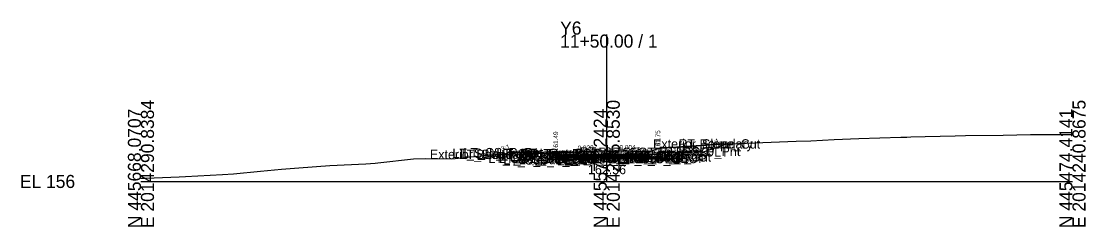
# Model space of a CAD drawing. Extents: x -26 to 203, y -10 to 4529.
# Drawn here: x -25.7 to 202.8, y 2990.3 to 3034.3 of the extents above; entities that cross this region are included whole.
import ezdxf

# ---------------------------------------------------------------- set-up
doc = ezdxf.new("R2010")
doc.units = 0
for name, color, linetype in [('Default', 7, 'Continuous'), ('Exist Cross Section Cell', 7, 'Continuous'), ('Exist XS Center Line Elevation Label', 7, 'Continuous'), ('Exist XS Ground Line', 7, 'Continuous'), ('Prop CMT Conc Surface', 7, 'Continuous'), ('Prop CMT Concrete Structures', 7, 'Continuous'), ('Prop CMT Pvmt Course 1', 7, 'Continuous'), ('Prop CMT Pvmt Course 1 CG', 7, 'Continuous'), ('Prop CMT Pvmt Course 2', 7, 'Continuous'), ('Prop CMT Pvmt Course 3', 7, 'Continuous'), ('Prop CMT Pvmt Surface', 7, 'Continuous'), ('Prop CMT Slope Grass', 7, 'Continuous'), ('Prop CMT Subgrade Earthwork', 7, 'Continuous'), ('Prop XS Earthwork Shape', 7, 'Continuous'), ('Prop XS Hydro Elevations', 7, 'Continuous'), ('Prop XS SE Text', 7, 'Continuous'), ('Prop XS Side Slope Text', 7, 'Continuous'), ('Scratch_Level_0', 7, 'Continuous')]:
    doc.layers.add(name, color=color, linetype=linetype)

msp = doc.modelspace()

# ---------------------------------------------------------------- linework, layer by layer
at = {"layer": 'Exist Cross Section Cell'}
for p, q in [((100, 3000), (100, 3031.48)), ((0, 3000), (100, 3000)), ((100, 3000), (200, 3000))]:
    msp.add_line(p, q, dxfattribs=at)
at = {"layer": 'Exist XS Ground Line'}
msp.add_lwpolyline([(0, 3000.72), (1.06, 3000.72), (8.22, 3001.02), (9.54, 3001.08), (17.48, 3001.5), (19.87, 3001.64), (25.69, 3002.24), (30.2, 3002.63), (33.9, 3002.94), (40.53, 3003.4), (48.25, 3003.8), (50.32, 3003.92), (50.86, 3003.96), (58.53, 3004.82), (61.19, 3004.92), (66.74, 3004.86), (71.52, 3005.33), (74.95, 3005.69), (85.22, 3006.07), (90.92, 3006.21), (96, 3006.42), (100.15, 3006.56), (105.56, 3006.5), (109.28, 3006.38), (110.84, 3007), (111.74, 3007.17), (120.27, 3007.73), (124.22, 3007.99), (128.31, 3008.14), (133.49, 3008.37), (140.64, 3008.62), (143.82, 3008.71), (148.85, 3008.97), (154.15, 3009.24), (163.13, 3009.46), (164.47, 3009.51), (165.27, 3009.53), (168.34, 3009.61), (174.8, 3009.78), (177.05, 3009.84), (185.13, 3009.92), (190.97, 3010.03), (196.73, 3010.09), (200, 3010.05)], dxfattribs=at)
at = {"layer": 'Prop CMT Conc Surface'}
for points in [[(89.06, 3005.49), (89.06, 3005.99), (88.56, 3005.99)], [(91.06, 3005.61), (89.06, 3005.49)], [(109, 3005.82), (111, 3005.75)], [(111, 3005.75), (111, 3006.25), (111.5, 3006.25)]]:
    msp.add_lwpolyline(points, dxfattribs=at)
at = {"layer": 'Prop CMT Concrete Structures'}
for points in [[(91.06, 3005.61), (89.06, 3005.49), (89.06, 3005.99), (88.56, 3005.99)], [(88.56, 3005.99), (88.56, 3004.98), (91.06, 3005.03)], [(91.06, 3005.03), (91.06, 3005.61)], [(109, 3005.82), (111, 3005.75), (111, 3006.25), (111.5, 3006.25)], [(111.5, 3006.25), (111.5, 3005.25), (109, 3005.24)], [(109, 3005.24), (109, 3005.82)]]:
    msp.add_lwpolyline(points, dxfattribs=at)
at = {"layer": 'Prop CMT Pvmt Course 1'}
for points in [[(100, 3005.79), (91.06, 3005.61)], [(91.06, 3005.61), (91.06, 3005.36)], [(91.06, 3005.36), (100, 3005.54)], [(100, 3005.79), (109, 3005.82)], [(100, 3005.54), (100, 3005.79)], [(100, 3005.54), (100, 3005.79)], [(109, 3005.57), (100, 3005.54)], [(109, 3005.82), (109, 3005.57)]]:
    msp.add_lwpolyline(points, dxfattribs=at)
msp.add_lwpolyline([(100, 3005.54), (100, 3005.67), (100, 3005.67), (100, 3005.54)], close=True, dxfattribs=at)
msp.add_lwpolyline([(100, 3005.54), (100, 3005.67), (100, 3005.67), (100, 3005.54)], close=True, dxfattribs=at)
at = {"layer": 'Prop CMT Pvmt Course 1 CG'}
for points in [[(109, 3005.24), (112, 3005.25), (112.33, 3004.92)], [(109, 3004.91), (109, 3005.24)], [(91.06, 3005.03), (88.06, 3004.97), (87.72, 3004.63)], [(87.72, 3004.63), (91.06, 3004.7)], [(91.06, 3004.7), (91.06, 3005.03)], [(112.33, 3004.92), (109, 3004.91)]]:
    msp.add_lwpolyline(points, dxfattribs=at)
at = {"layer": 'Prop CMT Pvmt Course 2'}
for points in [[(100, 3005.54), (91.06, 3005.36)], [(91.06, 3005.36), (91.06, 3005.03)], [(91.06, 3005.03), (100, 3005.21)], [(100, 3005.54), (109, 3005.57)], [(100, 3005.21), (100, 3005.54)], [(100, 3005.21), (100, 3005.54)], [(109, 3005.24), (100, 3005.21)], [(109, 3005.57), (109, 3005.24)]]:
    msp.add_lwpolyline(points, dxfattribs=at)
at = {"layer": 'Prop CMT Pvmt Course 3'}
for points in [[(100, 3005.21), (91.06, 3005.03)], [(100, 3005.21), (109, 3005.24)], [(100, 3004.88), (100, 3005.21)], [(100, 3004.88), (100, 3005.21)], [(109, 3005.24), (109, 3004.91)], [(91.06, 3005.03), (91.06, 3004.7)], [(91.06, 3004.7), (100, 3004.88)], [(109, 3004.91), (100, 3004.88)]]:
    msp.add_lwpolyline(points, dxfattribs=at)
at = {"layer": 'Prop CMT Pvmt Surface'}
for points in [[(100, 3005.79), (91.06, 3005.61)], [(100, 3005.79), (109, 3005.82)]]:
    msp.add_lwpolyline(points, dxfattribs=at)
at = {"layer": 'Prop CMT Slope Grass'}
for points in [[(111.5, 3006.25), (121, 3006.44), (125.82, 3008.05)], [(88.56, 3005.99), (79.06, 3006.18), (77.91, 3005.8)]]:
    msp.add_lwpolyline(points, dxfattribs=at)
at = {"layer": 'Prop CMT Subgrade Earthwork'}
for points in [[(91.06, 3004.7), (87.72, 3004.63), (86.31, 3006.04)], [(109, 3004.91), (112.33, 3004.92), (113.71, 3006.3)], [(100, 3004.88), (91.06, 3004.7)], [(100, 3004.88), (109, 3004.91)]]:
    msp.add_lwpolyline(points, dxfattribs=at)
at = {"layer": 'Prop XS Earthwork Shape'}
for points in [[(121, 3006.44), (125.82, 3008.05), (124.22, 3007.99), (120.27, 3007.73), (111.74, 3007.17), (110.84, 3007), (109.28, 3006.38), (105.56, 3006.5), (100.15, 3006.56), (96, 3006.42), (90.92, 3006.21), (85.22, 3006.07), (85.13, 3006.06), (86.31, 3006.04), (88.56, 3005.99), (89.06, 3005.99), (89.06, 3005.49), (91.06, 3005.61), (100, 3005.79), (109, 3005.82), (111, 3005.75), (111, 3006.25), (111.5, 3006.25), (113.71, 3006.3)], [(79.06, 3006.18), (77.91, 3005.8), (85.13, 3006.06)], [(109, 3004.91), (112.33, 3004.92), (113.71, 3006.3), (111.5, 3006.25), (111.5, 3005.25), (109, 3005.24), (109, 3005.82), (100, 3005.79), (91.06, 3005.61), (91.06, 3005.03), (88.56, 3004.98), (88.56, 3005.99), (86.31, 3006.04), (87.72, 3004.63), (91.06, 3004.7), (100, 3004.88)], [(91.06, 3005.03), (91.06, 3005.61), (89.06, 3005.49), (89.06, 3005.99), (88.56, 3005.99), (88.56, 3004.98)], [(111.5, 3006.25), (111.5, 3005.25), (109, 3005.24), (109, 3005.82), (111, 3005.75), (111, 3006.25)]]:
    msp.add_lwpolyline(points, close=True, dxfattribs=at)

# ---------------------------------------------------------------- texts
at = {"layer": 'Default'}
msp.add_text('-', height=0.0001, dxfattribs=at).set_placement((0, 3000))
at = {"layer": 'Exist Cross Section Cell'}
for s, p in [('Y6', (90, 3031.48)), ('11+50.00 / 1', (90, 3028.68)), ('EL 156', (-26, 2998.6))]:
    msp.add_text(s, height=2.8, dxfattribs=at).set_placement(p)
for s, p in [('E 2014290.8384', (2.8, 2990)), ('E 2014265.8530', (102.8, 2990)), ('E 2014240.8675', (202.8, 2990)), ('N 445668.0707', (0, 2990)), ('N 445571.2424', (100, 2990)), ('N 445474.4141', (200, 2990))]:
    msp.add_text(s, height=2.8, rotation=90, dxfattribs=at).set_placement(p)
at = {"layer": 'Exist XS Center Line Elevation Label'}
msp.add_text('162.56', height=2, dxfattribs=at).set_placement((95.97, 3001.56))
at = {"layer": 'Prop XS Hydro Elevations'}
for s, p in [('161.49', (89.56, 3006.49)), ('161.75', (111.5, 3006.75))]:
    msp.add_text(s, height=1, rotation=90, dxfattribs=at).set_placement(p)
at = {"layer": 'Prop XS SE Text'}
for s, rotation, p in [('0.020', 1.1458, (93.76, 3006.67)), ('0.004', 0.2022, (102.75, 3006.8))]:
    msp.add_text(s, height=1, rotation=rotation, dxfattribs=at).set_placement(p)
at = {"layer": 'Prop XS Side Slope Text'}
for p in [(77.5, 3006.45), (122.42, 3007.7)]:
    msp.add_text('3:1', height=1, rotation=18.4332, dxfattribs=at).set_placement(p)
at = {"layer": 'Scratch_Level_0'}
for s, p in [('Exterior Boundary', (109.96, 3007.05)), ('RT_Slope_Cut', (115.41, 3007.05)), ('Exterior Boundary', (62.05, 3004.8)), ('LT_Sub_Trench_Out_DLT', (66.88, 3005.04)), ('LT_Slope_Fill', (68.43, 3004.8)), ('LT_CSLP_Pnt', (69.23, 3005.18)), ('LT_CG1_Shelf_Out', (74.61, 3003.97)), ('LT_CG_Top_Face', (76.32, 3004.99)), ('LT_CG_Top_BOC', (76.84, 3004.99)), ('LT_CG_Bot_BOC', (76.88, 3003.98)), ('LT_CG_Top_Gut', (77.3, 3004.49)), ('LT_Sub_OEOP', (77.83, 3003.63)), ('LT_CG_Bot_IE', (80.97, 3004.03)), ('LT_Sub_OEOT', (81.14, 3003.7)), ('LT_PV2_OEOT', (81.23, 3004.36)), ('LT_PV3_OEOT', (81.23, 3004.03)), ('LT_PV1_OEOT', (81.8, 3004.61)), ('RT_Sub_OEEOP', (89.17, 3003.88)), ('LT_Sub_OEEOP', (89.21, 3003.88)), ('RT_PV2_OEEOP', (89.26, 3004.54)), ('RT_PV3_OEEOP', (89.26, 3004.21)), ('LT_PV2_OEEOP', (89.31, 3004.54)), ('LT_PV3_OEEOP', (89.31, 3004.21)), ('RT_PV1_OEEOP', (89.83, 3004.67)), ('LT_PV1_OEEOP', (89.87, 3004.67)), ('RT_PV2_IEEOP', (89.91, 3004.54)), ('LT_PV2_IEEOP', (89.95, 3004.54)), ('RT_PV1_IEEOP', (90.47, 3004.67)), ('LT_PV1_IEEOP', (90.52, 3004.67)), ('PV2_PGL', (93.91, 3004.54)), ('RT_Sub_Trench_Out_DLT', (94.23, 3005.3)), ('PV1_PGL', (94.47, 3004.79)), ('RT_CG_Top_Face', (98.21, 3005.25)), ('RT_CG1_Shelf_Out', (98.5, 3004.25)), ('RT_CG_Bot_IE', (98.87, 3004.24)), ('RT_Sub_OEOT', (99.03, 3003.91)), ('RT_PV2_OEOT', (99.13, 3004.57)), ('RT_PV3_OEOT', (99.13, 3004.24)), ('RT_CG_Top_Gut', (99.19, 3004.75)), ('RT_PV1_OEOT', (99.69, 3004.82)), ('RT_CG_Top_BOC', (99.74, 3005.25)), ('RT_CG_Bot_BOC', (99.77, 3004.25)), ('RT_Sub_OEOP', (102.39, 3003.92)), ('RT_CSLP_Pnt', (111.13, 3005.44))]:
    msp.add_text(s, height=2, dxfattribs=at).set_placement(p)

doc.saveas('drawing.dxf')
